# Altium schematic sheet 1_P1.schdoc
size 307 x 218 mm; Symbol: Drawing-Symbol_A4; Device: Drawing-Symbol_A4; @Project Name: 4s2p 18650 holder; @Page Count: 1; @Update Date: 2025-08-13; @Create Date: 2025-08-13; @Schematic Name: Schematic1; @Page No: 1; @Page Name: P1; Company: EasyEDA.com; Version: V1.0; Page Size: A4; @Create Time: 20:28:56; @Update Time: 22:28:56; Width: 1170; Height: 825; Region Start: 1; X Region Count: 6; Y Region Count: 4; Blade Width: 10; Title Block Position: 3; @Board Name: Board1
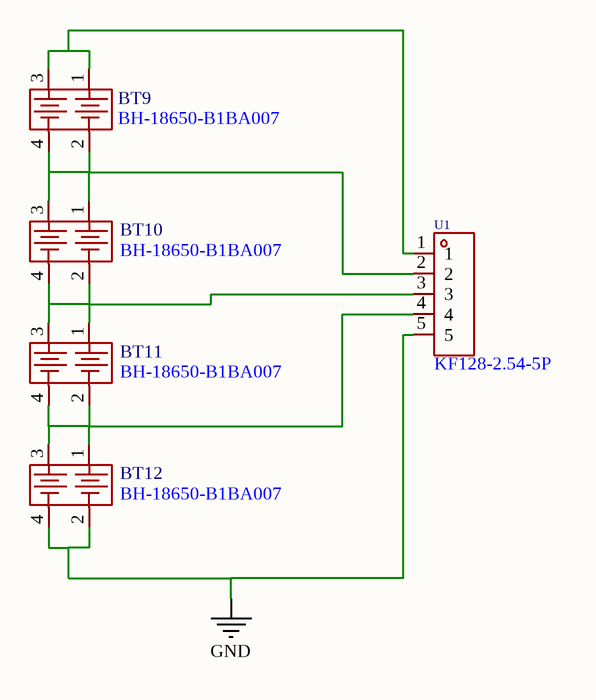
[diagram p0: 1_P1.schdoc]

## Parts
BT9  BH-18650-B1BA007  [BAT-SMD_BH-18650-B1BA007]
BT10  BH-18650-B1BA007  [BAT-SMD_BH-18650-B1BA007]
BT11  BH-18650-B1BA007  [BAT-SMD_BH-18650-B1BA007]
BT12  BH-18650-B1BA007  [BAT-SMD_BH-18650-B1BA007]
U1  KF128-2.54-5P  [CONN-TH_5P-P2.54_KF128-2.54-5P]

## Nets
GND: BT12.2 BT12.4 U1.5
NetBT9_1: BT9.1 BT9.3 U1.1
NetBT9_2: BT9.2 BT9.4 BT10.1 BT10.3 U1.2
NetBT10_2: BT10.2 BT10.4 BT11.1 BT11.3 U1.3
NetBT11_2: BT11.2 BT11.4 BT12.1 BT12.3 U1.4

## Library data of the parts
BT9-BT12 = BH-18650-B1BA007: Manufacturer: MYOUNG(美阳); Add into BOM: yes; Connector Type: Battery box
U1 = KF128-2.54-5P: Manufacturer: KEFA(科发); Add into BOM: yes; Structure: 1x5P; Pitch: 2.54mm; Current Rating (Max): 8A; Voltage Rating (Max): 130V; Wire Gauge - AWG: 18~26; Wire Gauge - mm2: 1; Number of PINs Per Row: 5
